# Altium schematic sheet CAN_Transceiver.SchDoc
size A; SheetNumber: 5; SheetTotal: 5; Parameter 1: 120
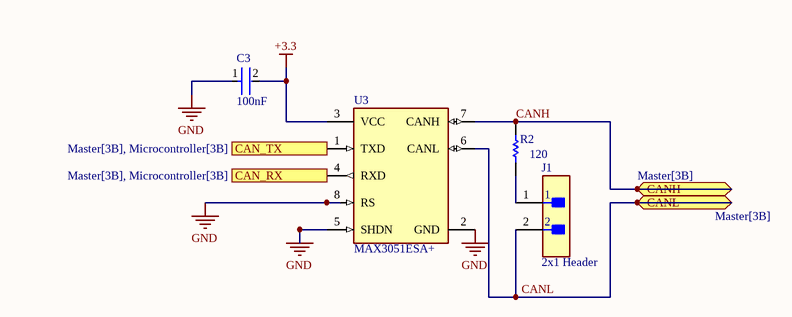
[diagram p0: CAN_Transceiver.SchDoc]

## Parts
C3  100nF  [CAPC0603(1608)100_L]
J1  2x1 Header  [0.1" Header 2x1-Footprint]
R2  120  [RESC2013X50X30ML20T20]
U3  MAX3051ESA+  [FP-S8-4-IPC_B]

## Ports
CAN_RX (see Master[3B], Microcontroller[3B]), CAN_TX (see Master[3B], Microcontroller[3B]), CANH (bidir, see Master[3B]), CANL (bidir, see Master[3B])

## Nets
+3.3: C3.2 U3.3(VCC)
GND: C3.1 U3.2(GND) U3.5(SHDN) U3.8(RS)
CAN_RX: U3.4(RXD) ; port CAN_RX
CAN_TX: U3.1(TXD) ; port CAN_TX
CANH: R2.2 U3.7(CANH) ; port CANH
CANL: J1.2 U3.6(CANL) ; port CANL
NetJ1_1: J1.1 R2.1

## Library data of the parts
C3 = CMP-001-00083-4: GENERIC CAPACITOR 0805 or 0603(1608)
J1 = CMP-002-00002-10: Board Connector, 2 Contact(s), 1 Row(s), Male, Straight, 0.1 inch and 0.079 inch Pitch, Solder Terminal, Locking, Black Insulator
R2 = CMP-009-00177-4: Surface Mount 0805 Resistor
U3 = CMP-015-00014-1: MAX3051 Series 3.3 V 1 Mbps Low-Supply-Current CAN Transceiver - SOIC-8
